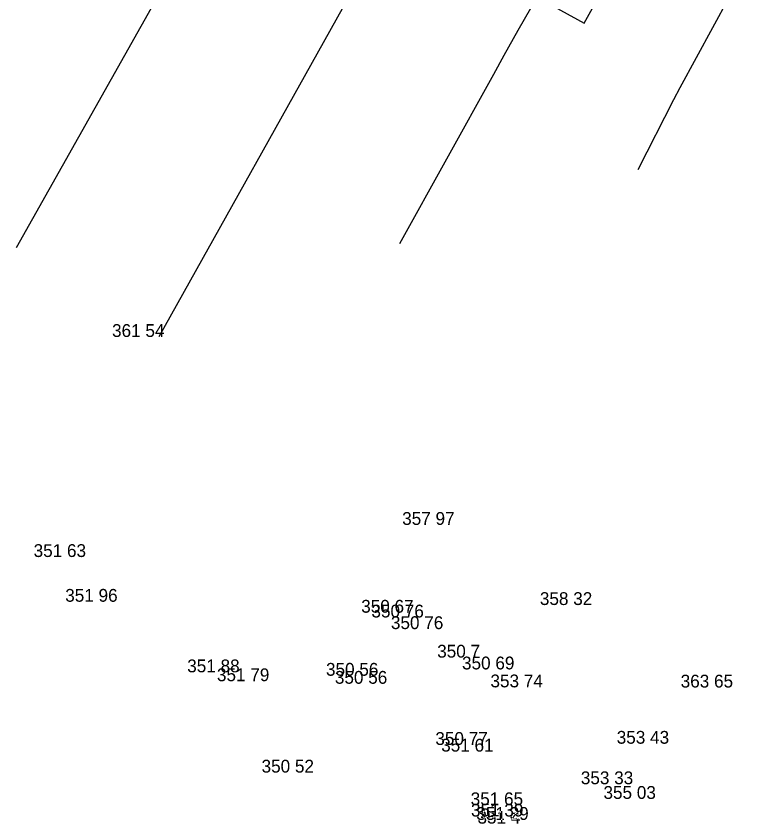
# Model space of a CAD drawing. Extents: x -688316 to -688024, y -973785 to -973591.
# Drawn here: x -688190.35 to -688147, y -973766.44 to -973719.16 of the extents above; entities that cross this region are included whole.
import ezdxf

# ---------------------------------------------------------------- set-up
doc = ezdxf.new("R2010")
doc.units = 0
for name, color, linetype in [('Vrstva 3', 7, 'Continuous'), ('Vrstva 5', 7, 'Continuous'), ('Vrstva 7', 7, 'Continuous')]:
    doc.layers.add(name, color=color, linetype=linetype)

msp = doc.modelspace()

# ---------------------------------------------------------------- linework, layer by layer
at = {"layer": 'Vrstva 5'}
msp.add_lwpolyline([(-688159.87, -973718.03), (-688157.1, -973719.57), (-688153.63, -973713.29), (-688156.36, -973711.78)], dxfattribs=at)
at = {"layer": 'Vrstva 7'}
for p, q in [((-688176.77, -973708.56), (-688190.35, -973732.73)), ((-688151.48, -973723.34), (-688147, -973715.07)), ((-688170.68, -973717.65), (-688181.99, -973737.94)), ((-688159.87, -973718.03), (-688160.98, -973720)), ((-688160.98, -973720), (-688161.8, -973721.47)), ((-688161.8, -973721.47), (-688162.41, -973722.58)), ((-688162.41, -973722.58), (-688167.91, -973732.48)), ((-688151.85, -973724.03), (-688151.48, -973723.34)), ((-688153.95, -973728.13), (-688151.85, -973724.03))]:
    msp.add_line(p, q, dxfattribs=at)

# ---------------------------------------------------------------- texts
at = {"layer": 'Vrstva 3'}
for s, p in [('361 54 ', (-688184.738, -973737.94)), ('361 54 ', (-688184.738, -973737.94)), ('361 54 ', (-688184.738, -973737.94)), ('361 54 ', (-688184.738, -973737.94)), ('361 54 ', (-688184.738, -973737.94)), ('361 54 ', (-688184.738, -973737.94)), ('361 54 ', (-688184.738, -973737.94)), ('357 97 ', (-688167.757, -973748.94)), ('357 97 ', (-688167.757, -973748.94)), ('357 97 ', (-688167.757, -973748.94)), ('357 97 ', (-688167.757, -973748.94)), ('357 97 ', (-688167.757, -973748.94)), ('357 97 ', (-688167.757, -973748.94)), ('357 97 ', (-688167.757, -973748.94)), ('351 63 ', (-688189.328, -973750.82)), ('351 63 ', (-688189.328, -973750.82)), ('351 63 ', (-688189.328, -973750.82)), ('351 63 ', (-688189.328, -973750.82)), ('351 63 ', (-688189.328, -973750.82)), ('351 63 ', (-688189.328, -973750.82)), ('351 63 ', (-688189.328, -973750.82)), ('351 96 ', (-688187.479, -973753.44)), ('351 96 ', (-688187.479, -973753.44)), ('351 96 ', (-688187.479, -973753.44)), ('351 96 ', (-688187.479, -973753.44)), ('351 96 ', (-688187.479, -973753.44)), ('351 96 ', (-688187.479, -973753.44)), ('351 96 ', (-688187.479, -973753.44)), ('358 32 ', (-688159.699, -973753.63)), ('358 32 ', (-688159.699, -973753.63)), ('358 32 ', (-688159.699, -973753.63)), ('358 32 ', (-688159.699, -973753.63)), ('358 32 ', (-688159.699, -973753.63)), ('358 32 ', (-688159.699, -973753.63)), ('358 32 ', (-688159.699, -973753.63)), ('350 67 ', (-688170.156, -973754.08)), ('350 67 ', (-688170.156, -973754.08)), ('350 67 ', (-688170.156, -973754.08)), ('350 67 ', (-688170.156, -973754.08)), ('350 67 ', (-688170.156, -973754.08)), ('350 67 ', (-688170.156, -973754.08)), ('350 67 ', (-688170.156, -973754.08)), ('350 76 ', (-688169.557, -973754.36)), ('350 76 ', (-688169.557, -973754.36)), ('350 76 ', (-688169.557, -973754.36)), ('350 76 ', (-688169.557, -973754.36)), ('350 76 ', (-688169.557, -973754.36)), ('350 76 ', (-688169.557, -973754.36)), ('350 76 ', (-688169.557, -973754.36)), ('350 76 ', (-688168.417, -973755.04)), ('350 76 ', (-688168.417, -973755.04)), ('350 76 ', (-688168.417, -973755.04)), ('350 76 ', (-688168.417, -973755.04)), ('350 76 ', (-688168.417, -973755.04)), ('350 76 ', (-688168.417, -973755.04)), ('350 76 ', (-688168.417, -973755.04)), ('350 7  ', (-688165.708, -973756.71)), ('350 7  ', (-688165.708, -973756.71)), ('350 7  ', (-688165.708, -973756.71)), ('350 7  ', (-688165.708, -973756.71)), ('350 7  ', (-688165.708, -973756.71)), ('350 7  ', (-688165.708, -973756.71)), ('350 7  ', (-688165.708, -973756.71)), ('351 88 ', (-688180.339, -973757.57)), ('351 88 ', (-688180.339, -973757.57)), ('351 88 ', (-688180.339, -973757.57)), ('351 88 ', (-688180.339, -973757.57)), ('351 88 ', (-688180.339, -973757.57)), ('351 88 ', (-688180.339, -973757.57)), ('351 88 ', (-688180.339, -973757.57)), ('350 69 ', (-688164.256, -973757.4)), ('350 69 ', (-688164.256, -973757.4)), ('350 69 ', (-688164.256, -973757.4)), ('350 69 ', (-688164.256, -973757.4)), ('350 69 ', (-688164.256, -973757.4)), ('350 69 ', (-688164.256, -973757.4)), ('350 69 ', (-688164.256, -973757.4)), ('351 79 ', (-688178.599, -973758.09)), ('351 79 ', (-688178.599, -973758.09)), ('351 79 ', (-688178.599, -973758.09)), ('351 79 ', (-688178.599, -973758.09)), ('351 79 ', (-688178.599, -973758.09)), ('351 79 ', (-688178.599, -973758.09)), ('351 79 ', (-688178.599, -973758.09)), ('350 56 ', (-688172.217, -973757.77)), ('350 56 ', (-688172.217, -973757.77)), ('350 56 ', (-688172.217, -973757.77)), ('350 56 ', (-688172.217, -973757.77)), ('350 56 ', (-688172.217, -973757.77)), ('350 56 ', (-688172.217, -973757.77)), ('350 56 ', (-688172.217, -973757.77)), ('350 56 ', (-688171.697, -973758.24)), ('350 56 ', (-688171.697, -973758.24)), ('350 56 ', (-688171.697, -973758.24)), ('350 56 ', (-688171.697, -973758.24)), ('350 56 ', (-688171.697, -973758.24)), ('350 56 ', (-688171.697, -973758.24)), ('350 56 ', (-688171.697, -973758.24)), ('353 74 ', (-688162.591, -973758.45)), ('353 74 ', (-688162.591, -973758.45)), ('353 74 ', (-688162.591, -973758.45)), ('353 74 ', (-688162.591, -973758.45)), ('353 74 ', (-688162.591, -973758.45)), ('353 74 ', (-688162.591, -973758.45)), ('353 74 ', (-688162.591, -973758.45)), ('363 65 ', (-688151.458, -973758.46)), ('363 65 ', (-688151.458, -973758.46)), ('363 65 ', (-688151.458, -973758.46)), ('363 65 ', (-688151.458, -973758.46)), ('363 65 ', (-688151.458, -973758.46)), ('363 65 ', (-688151.458, -973758.46)), ('363 65 ', (-688151.458, -973758.46)), ('350 77 ', (-688165.817, -973761.82)), ('350 77 ', (-688165.817, -973761.82)), ('350 77 ', (-688165.817, -973761.82)), ('350 77 ', (-688165.817, -973761.82)), ('350 77 ', (-688165.817, -973761.82)), ('350 77 ', (-688165.817, -973761.82)), ('350 77 ', (-688165.817, -973761.82)), ('353 43 ', (-688155.201, -973761.75)), ('353 43 ', (-688155.201, -973761.75)), ('353 43 ', (-688155.201, -973761.75)), ('353 43 ', (-688155.201, -973761.75)), ('353 43 ', (-688155.201, -973761.75)), ('353 43 ', (-688155.201, -973761.75)), ('353 43 ', (-688155.201, -973761.75)), ('351 61 ', (-688165.474, -973762.21)), ('351 61 ', (-688165.474, -973762.21)), ('351 61 ', (-688165.474, -973762.21)), ('351 61 ', (-688165.474, -973762.21)), ('351 61 ', (-688165.474, -973762.21)), ('351 61 ', (-688165.474, -973762.21)), ('351 61 ', (-688165.474, -973762.21)), ('350 52 ', (-688175.987, -973763.44)), ('350 52 ', (-688175.987, -973763.44)), ('350 52 ', (-688175.987, -973763.44)), ('350 52 ', (-688175.987, -973763.44)), ('350 52 ', (-688175.987, -973763.44)), ('350 52 ', (-688175.987, -973763.44)), ('350 52 ', (-688175.987, -973763.44)), ('353 33 ', (-688157.302, -973764.12)), ('353 33 ', (-688157.302, -973764.12)), ('353 33 ', (-688157.302, -973764.12)), ('353 33 ', (-688157.302, -973764.12)), ('353 33 ', (-688157.302, -973764.12)), ('353 33 ', (-688157.302, -973764.12)), ('353 33 ', (-688157.302, -973764.12)), ('355 03 ', (-688155.977, -973764.98)), ('355 03 ', (-688155.977, -973764.98)), ('355 03 ', (-688155.977, -973764.98)), ('355 03 ', (-688155.977, -973764.98)), ('355 03 ', (-688155.977, -973764.98)), ('355 03 ', (-688155.977, -973764.98)), ('355 03 ', (-688155.977, -973764.98)), ('351 65 ', (-688163.748, -973765.35)), ('351 65 ', (-688163.748, -973765.35)), ('351 65 ', (-688163.748, -973765.35)), ('351 65 ', (-688163.748, -973765.35)), ('351 65 ', (-688163.748, -973765.35)), ('351 65 ', (-688163.748, -973765.35)), ('351 65 ', (-688163.748, -973765.35)), ('351 39 ', (-688163.731, -973766.01)), ('351 39 ', (-688163.731, -973766.01)), ('351 39 ', (-688163.731, -973766.01)), ('351 39 ', (-688163.731, -973766.01)), ('351 39 ', (-688163.731, -973766.01)), ('351 39 ', (-688163.731, -973766.01)), ('351 39 ', (-688163.731, -973766.01)), ('351 39 ', (-688163.421, -973766.21)), ('351 39 ', (-688163.421, -973766.21)), ('351 39 ', (-688163.421, -973766.21)), ('351 39 ', (-688163.421, -973766.21)), ('351 39 ', (-688163.421, -973766.21)), ('351 39 ', (-688163.421, -973766.21)), ('351 39 ', (-688163.421, -973766.21)), ('351 4  ', (-688163.351, -973766.43)), ('351 4  ', (-688163.351, -973766.43)), ('351 4  ', (-688163.351, -973766.43)), ('351 4  ', (-688163.351, -973766.43)), ('351 4  ', (-688163.351, -973766.43)), ('351 4  ', (-688163.351, -973766.43)), ('351 4  ', (-688163.351, -973766.43))]:
    msp.add_text(s, height=0.75, dxfattribs=at).set_placement(p)

doc.saveas('drawing.dxf')
